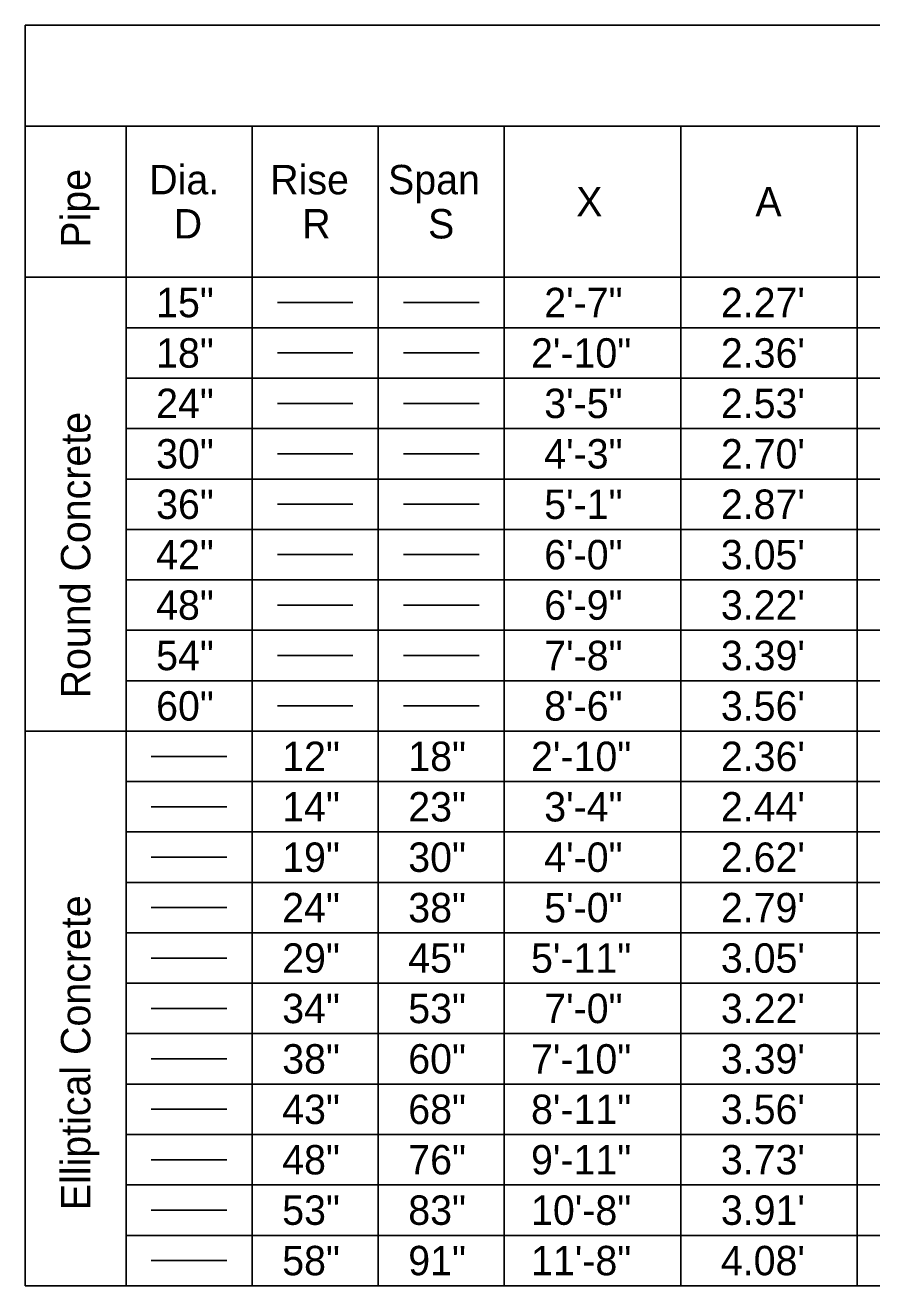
# Model space of a CAD drawing. Extents: x -1.3 to 14.5, y 0 to 8.2.
# Drawn here: x 2 to 4.015, y 5.227 to 8.227 of the extents above; entities that cross this region are included whole.
import ezdxf

# ---------------------------------------------------------------- set-up
doc = ezdxf.new("R2010")
doc.units = 0
doc.layers.add('TextNotes', color=7, linetype='Continuous')
doc.layers.add('TextTables', color=7, linetype='Continuous')

msp = doc.modelspace()

# ---------------------------------------------------------------- linework, layer by layer
at = {"layer": 'TextTables'}
for p, q in [((2, 8.2274), (13.4, 8.2274)), ((2.6, 7.5674), (2.78, 7.5674)), ((2.9, 7.5674), (3.08, 7.5674)), ((2.6, 7.4474), (2.78, 7.4474)), ((2.9, 7.4474), (3.08, 7.4474)), ((2.6, 7.3274), (2.78, 7.3274)), ((2.9, 7.3274), (3.08, 7.3274)), ((2.6, 7.2074), (2.78, 7.2074)), ((2.9, 7.2074), (3.08, 7.2074)), ((2.6, 7.0874), (2.78, 7.0874)), ((2.9, 7.0874), (3.08, 7.0874)), ((2.6, 6.9674), (2.78, 6.9674)), ((2.9, 6.9674), (3.08, 6.9674)), ((2.6, 6.8474), (2.78, 6.8474)), ((2.9, 6.8474), (3.08, 6.8474)), ((2.6, 6.7274), (2.78, 6.7274)), ((2.9, 6.7274), (3.08, 6.7274)), ((2.6, 6.6074), (2.78, 6.6074)), ((2.9, 6.6074), (3.08, 6.6074)), ((2.3, 6.4874), (2.48, 6.4874)), ((2.3, 6.3674), (2.48, 6.3674)), ((2.3, 6.2474), (2.48, 6.2474)), ((2.3, 6.1274), (2.48, 6.1274)), ((2.3, 6.0074), (2.48, 6.0074)), ((2.3, 5.8874), (2.48, 5.8874)), ((2.3, 5.7674), (2.48, 5.7674)), ((2.3, 5.6474), (2.48, 5.6474)), ((2.3, 5.5274), (2.48, 5.5274)), ((2.3, 5.4074), (2.48, 5.4074)), ((2.3, 5.2874), (2.48, 5.2874))]:
    msp.add_line(p, q, dxfattribs=at)
for points in [[(2, 8.2274), (2, 7.9874), (2, 7.6274), (2, 6.5474), (2, 5.2274)], [(13.4, 7.9874), (11.72, 7.9874), (10.04, 7.9874), (8.36, 7.9874), (8, 7.9874), (6.32, 7.9874), (5.96, 7.9874), (5.6, 7.9874), (5.36, 7.9874), (4.88, 7.9874), (4.46, 7.9874), (3.98, 7.9874), (3.56, 7.9874), (3.14, 7.9874), (2.84, 7.9874), (2.54, 7.9874), (2.24, 7.9874), (2, 7.9874)], [(2.24, 7.9874), (2.24, 7.6274), (2.24, 7.5074), (2.24, 7.3874), (2.24, 7.2674), (2.24, 7.1474), (2.24, 7.0274), (2.24, 6.9074), (2.24, 6.7874), (2.24, 6.6674), (2.24, 6.5474), (2.24, 6.4274), (2.24, 6.3074), (2.24, 6.1874), (2.24, 6.0674), (2.24, 5.9474), (2.24, 5.8274), (2.24, 5.7074), (2.24, 5.5874), (2.24, 5.4674), (2.24, 5.3474), (2.24, 5.2274)], [(2.54, 7.9874), (2.54, 7.6274), (2.54, 7.5074), (2.54, 7.3874), (2.54, 7.2674), (2.54, 7.1474), (2.54, 7.0274), (2.54, 6.9074), (2.54, 6.7874), (2.54, 6.6674), (2.54, 6.5474), (2.54, 6.4274), (2.54, 6.3074), (2.54, 6.1874), (2.54, 6.0674), (2.54, 5.9474), (2.54, 5.8274), (2.54, 5.7074), (2.54, 5.5874), (2.54, 5.4674), (2.54, 5.3474), (2.54, 5.2274)], [(2.84, 7.9874), (2.84, 7.6274), (2.84, 7.5074), (2.84, 7.3874), (2.84, 7.2674), (2.84, 7.1474), (2.84, 7.0274), (2.84, 6.9074), (2.84, 6.7874), (2.84, 6.6674), (2.84, 6.5474), (2.84, 6.4274), (2.84, 6.3074), (2.84, 6.1874), (2.84, 6.0674), (2.84, 5.9474), (2.84, 5.8274), (2.84, 5.7074), (2.84, 5.5874), (2.84, 5.4674), (2.84, 5.3474), (2.84, 5.2274)], [(3.14, 7.9874), (3.14, 7.6274), (3.14, 7.5074), (3.14, 7.3874), (3.14, 7.2674), (3.14, 7.1474), (3.14, 7.0274), (3.14, 6.9074), (3.14, 6.7874), (3.14, 6.6674), (3.14, 6.5474), (3.14, 6.4274), (3.14, 6.3074), (3.14, 6.1874), (3.14, 6.0674), (3.14, 5.9474), (3.14, 5.8274), (3.14, 5.7074), (3.14, 5.5874), (3.14, 5.4674), (3.14, 5.3474), (3.14, 5.2274)], [(3.56, 7.9874), (3.56, 7.6274), (3.56, 7.5074), (3.56, 7.3874), (3.56, 7.2674), (3.56, 7.1474), (3.56, 7.0274), (3.56, 6.9074), (3.56, 6.7874), (3.56, 6.6674), (3.56, 6.5474), (3.56, 6.4274), (3.56, 6.3074), (3.56, 6.1874), (3.56, 6.0674), (3.56, 5.9474), (3.56, 5.8274), (3.56, 5.7074), (3.56, 5.5874), (3.56, 5.4674), (3.56, 5.3474), (3.56, 5.2274)], [(3.98, 7.9874), (3.98, 7.6274), (3.98, 7.5074), (3.98, 7.3874), (3.98, 7.2674), (3.98, 7.1474), (3.98, 7.0274), (3.98, 6.9074), (3.98, 6.7874), (3.98, 6.6674), (3.98, 6.5474), (3.98, 6.4274), (3.98, 6.3074), (3.98, 6.1874), (3.98, 6.0674), (3.98, 5.9474), (3.98, 5.8274), (3.98, 5.7074), (3.98, 5.5874), (3.98, 5.4674), (3.98, 5.3474), (3.98, 5.2274)], [(2, 7.6274), (2.24, 7.6274), (2.54, 7.6274), (2.84, 7.6274), (3.14, 7.6274), (3.56, 7.6274), (3.98, 7.6274), (4.46, 7.6274)], [(2.24, 7.5074), (2.54, 7.5074), (2.84, 7.5074), (3.14, 7.5074), (3.56, 7.5074), (3.98, 7.5074), (4.46, 7.5074)], [(2.24, 7.3874), (2.54, 7.3874), (2.84, 7.3874), (3.14, 7.3874), (3.56, 7.3874), (3.98, 7.3874), (4.46, 7.3874)], [(2.24, 7.2674), (2.54, 7.2674), (2.84, 7.2674), (3.14, 7.2674), (3.56, 7.2674), (3.98, 7.2674), (4.46, 7.2674)], [(2.24, 7.1474), (2.54, 7.1474), (2.84, 7.1474), (3.14, 7.1474), (3.56, 7.1474), (3.98, 7.1474), (4.46, 7.1474)], [(2.24, 7.0274), (2.54, 7.0274), (2.84, 7.0274), (3.14, 7.0274), (3.56, 7.0274), (3.98, 7.0274), (4.46, 7.0274)], [(2.24, 6.9074), (2.54, 6.9074), (2.84, 6.9074), (3.14, 6.9074), (3.56, 6.9074), (3.98, 6.9074), (4.46, 6.9074)], [(2.24, 6.7874), (2.54, 6.7874), (2.84, 6.7874), (3.14, 6.7874), (3.56, 6.7874), (3.98, 6.7874), (4.46, 6.7874)], [(2.24, 6.6674), (2.54, 6.6674), (2.84, 6.6674), (3.14, 6.6674), (3.56, 6.6674), (3.98, 6.6674), (4.46, 6.6674)], [(2, 6.5474), (2.24, 6.5474), (2.54, 6.5474), (2.84, 6.5474), (3.14, 6.5474), (3.56, 6.5474), (3.98, 6.5474), (4.46, 6.5474)], [(2.24, 6.4274), (2.54, 6.4274), (2.84, 6.4274), (3.14, 6.4274), (3.56, 6.4274), (3.98, 6.4274), (4.46, 6.4274)], [(2.24, 6.3074), (2.54, 6.3074), (2.84, 6.3074), (3.14, 6.3074), (3.56, 6.3074), (3.98, 6.3074), (4.46, 6.3074)], [(2.24, 6.1874), (2.54, 6.1874), (2.84, 6.1874), (3.14, 6.1874), (3.56, 6.1874), (3.98, 6.1874), (4.46, 6.1874)], [(2.24, 6.0674), (2.54, 6.0674), (2.84, 6.0674), (3.14, 6.0674), (3.56, 6.0674), (3.98, 6.0674), (4.46, 6.0674)], [(2.24, 5.9474), (2.54, 5.9474), (2.84, 5.9474), (3.14, 5.9474), (3.56, 5.9474), (3.98, 5.9474), (4.46, 5.9474)], [(2.24, 5.8274), (2.54, 5.8274), (2.84, 5.8274), (3.14, 5.8274), (3.56, 5.8274), (3.98, 5.8274), (4.46, 5.8274)], [(2.24, 5.7074), (2.54, 5.7074), (2.84, 5.7074), (3.14, 5.7074), (3.56, 5.7074), (3.98, 5.7074), (4.46, 5.7074)], [(2.24, 5.5874), (2.54, 5.5874), (2.84, 5.5874), (3.14, 5.5874), (3.56, 5.5874), (3.98, 5.5874), (4.46, 5.5874)], [(2.24, 5.4674), (2.54, 5.4674), (2.84, 5.4674), (3.14, 5.4674), (3.56, 5.4674), (3.98, 5.4674), (4.46, 5.4674)], [(2.24, 5.3474), (2.54, 5.3474), (2.84, 5.3474), (3.14, 5.3474), (3.56, 5.3474), (3.98, 5.3474), (4.46, 5.3474)], [(2, 5.2274), (2.24, 5.2274), (2.54, 5.2274), (2.84, 5.2274), (3.14, 5.2274), (3.56, 5.2274), (3.98, 5.2274), (4.46, 5.2274)]]:
    msp.add_lwpolyline(points, dxfattribs=at)

# ---------------------------------------------------------------- texts
at = {"layer": 'TextNotes'}
for s, p in [('Dia.', (2.2952, 7.8249)), ('Rise', (2.5831, 7.8249)), ('Span', (2.8634, 7.8249)), ('X', (3.3112, 7.7724)), ('A', (3.7375, 7.7724)), ('D', (2.3534, 7.7199)), ('R', (2.6592, 7.7199)), ('S', (2.9586, 7.7199))]:
    msp.add_text(s, height=0.07, dxfattribs=at).set_placement(p)
for s, rotation, p in [('Pipe', 90, (2.155, 7.6979)), ('15"', 0, (2.3115, 7.5324)), ('2\'-7"', 0, (3.2351, 7.5324)), ("2.27'", 0, (3.6554, 7.5324)), ('18"', 0, (2.3115, 7.4124)), ('2\'-10"', 0, (3.2037, 7.4124)), ("2.36'", 0, (3.6554, 7.4124)), ('24"', 0, (2.3115, 7.2924)), ('3\'-5"', 0, (3.2351, 7.2924)), ("2.53'", 0, (3.6554, 7.2924)), ('Round Concrete', 90, (2.155, 6.6254)), ('30"', 0, (2.3115, 7.1724)), ('4\'-3"', 0, (3.2351, 7.1724)), ("2.70'", 0, (3.6554, 7.1724)), ('36"', 0, (2.3115, 7.0524)), ('5\'-1"', 0, (3.2351, 7.0524)), ("2.87'", 0, (3.6554, 7.0524)), ('42"', 0, (2.3115, 6.9324)), ('6\'-0"', 0, (3.2351, 6.9324)), ("3.05'", 0, (3.6554, 6.9324)), ('48"', 0, (2.3115, 6.8124)), ('6\'-9"', 0, (3.2351, 6.8124)), ("3.22'", 0, (3.6554, 6.8124)), ('54"', 0, (2.3115, 6.6924)), ('7\'-8"', 0, (3.2351, 6.6924)), ("3.39'", 0, (3.6554, 6.6924)), ('60"', 0, (2.3115, 6.5724)), ('8\'-6"', 0, (3.2351, 6.5724)), ("3.56'", 0, (3.6554, 6.5724)), ('12"', 0, (2.6115, 6.4524)), ('18"', 0, (2.9115, 6.4524)), ('2\'-10"', 0, (3.2037, 6.4524)), ("2.36'", 0, (3.6554, 6.4524)), ('14"', 0, (2.6115, 6.3324)), ('23"', 0, (2.9115, 6.3324)), ('3\'-4"', 0, (3.2351, 6.3324)), ("2.44'", 0, (3.6554, 6.3324)), ('19"', 0, (2.6115, 6.2124)), ('30"', 0, (2.9115, 6.2124)), ('4\'-0"', 0, (3.2351, 6.2124)), ("2.62'", 0, (3.6554, 6.2124)), ('Elliptical Concrete', 90, (2.155, 5.4074)), ('24"', 0, (2.6115, 6.0924)), ('38"', 0, (2.9115, 6.0924)), ('5\'-0"', 0, (3.2351, 6.0924)), ("2.79'", 0, (3.6554, 6.0924)), ('29"', 0, (2.6115, 5.9724)), ('45"', 0, (2.9115, 5.9724)), ('5\'-11"', 0, (3.2037, 5.9724)), ("3.05'", 0, (3.6554, 5.9724)), ('34"', 0, (2.6115, 5.8524)), ('53"', 0, (2.9115, 5.8524)), ('7\'-0"', 0, (3.2351, 5.8524)), ("3.22'", 0, (3.6554, 5.8524)), ('38"', 0, (2.6115, 5.7324)), ('60"', 0, (2.9115, 5.7324)), ('7\'-10"', 0, (3.2037, 5.7324)), ("3.39'", 0, (3.6554, 5.7324)), ('43"', 0, (2.6115, 5.6124)), ('68"', 0, (2.9115, 5.6124)), ('8\'-11"', 0, (3.2037, 5.6124)), ("3.56'", 0, (3.6554, 5.6124)), ('48"', 0, (2.6115, 5.4924)), ('76"', 0, (2.9115, 5.4924)), ('9\'-11"', 0, (3.2037, 5.4924)), ("3.73'", 0, (3.6554, 5.4924)), ('53"', 0, (2.6115, 5.3724)), ('83"', 0, (2.9115, 5.3724)), ('10\'-8"', 0, (3.2037, 5.3724)), ("3.91'", 0, (3.6554, 5.3724)), ('58"', 0, (2.6115, 5.2524)), ('91"', 0, (2.9115, 5.2524)), ('11\'-8"', 0, (3.2037, 5.2524)), ("4.08'", 0, (3.6554, 5.2524))]:
    msp.add_text(s, height=0.07, rotation=rotation, dxfattribs=at).set_placement(p)

doc.saveas('drawing.dxf')
